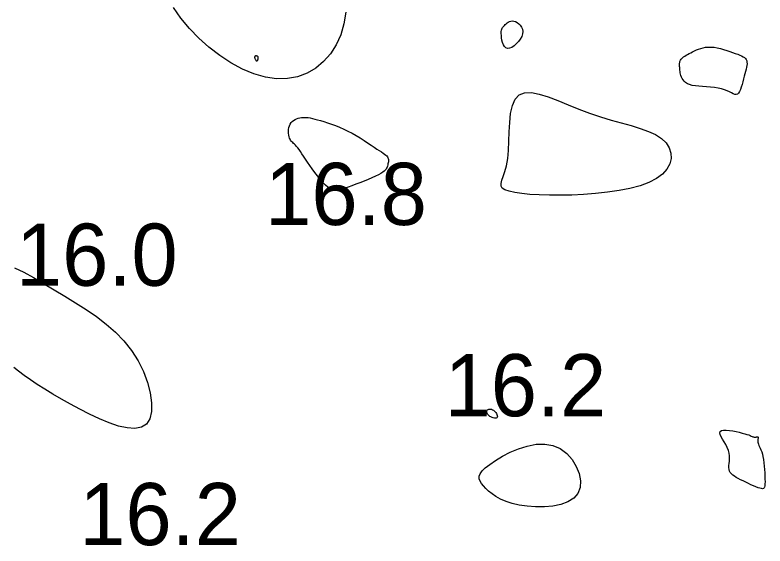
# Model space of a CAD drawing. Extents: x 3040093 to 3056816, y 408076 to 509144.
# Drawn here: x 3045926.6 to 3045987, y 434548.7 to 434591.4 of the extents above; entities that cross this region are included whole.
import ezdxf

# ---------------------------------------------------------------- set-up
doc = ezdxf.new("R2010")
doc.units = 0
doc.layers.add('V-CHAN-CONT-EL17', color=7, linetype='Continuous')
doc.layers.add('V-TOPO-SOUN-0610', color=7, linetype='Continuous')

msp = doc.modelspace()

# ---------------------------------------------------------------- linework, layer by layer
at = {"layer": 'V-CHAN-CONT-EL17'}
for points in [[(3045953.24, 434591.64), (3045953.079, 434590.693), (3045952.821, 434589.81), (3045952.46, 434589.003), (3045951.999, 434588.283), (3045951.448, 434587.657), (3045950.817, 434587.136), (3045950.113, 434586.728), (3045949.347, 434586.441), (3045948.527, 434586.286), (3045947.662, 434586.272), (3045946.762, 434586.403), (3045945.841, 434586.67), (3045944.912, 434587.058), (3045943.99, 434587.553), (3045943.088, 434588.142), (3045942.221, 434588.811), (3045941.403, 434589.545), (3045940.648, 434590.331), (3045939.967, 434591.156), (3045939.356, 434592.013)], [(3045926.587, 434571.056), (3045927.318, 434570.708), (3045928.098, 434570.281), (3045928.914, 434569.8), (3045929.757, 434569.293), (3045930.616, 434568.778), (3045931.479, 434568.253), (3045932.331, 434567.711), (3045933.161, 434567.141), (3045933.956, 434566.535), (3045934.701, 434565.885), (3045935.386, 434565.182), (3045935.996, 434564.417), (3045936.519, 434563.588), (3045936.949, 434562.722), (3045937.279, 434561.848), (3045937.501, 434560.999), (3045937.611, 434560.207), (3045937.6, 434559.503), (3045937.463, 434558.919), (3045937.194, 434558.487), (3045936.789, 434558.23), (3045936.266, 434558.134), (3045935.647, 434558.176), (3045934.951, 434558.334), (3045934.201, 434558.586), (3045933.417, 434558.91), (3045932.621, 434559.282), (3045931.833, 434559.68), (3045931.073, 434560.086), (3045930.347, 434560.492), (3045929.658, 434560.894), (3045929.011, 434561.291), (3045928.409, 434561.677), (3045927.855, 434562.05), (3045927.355, 434562.406), (3045926.911, 434562.741), (3045926.526, 434563.053)]]:
    msp.add_lwpolyline(points, dxfattribs=at)
for points in [[(3045966.1, 434588.76), (3045965.99, 434588.863), (3045965.904, 434589.008), (3045965.838, 434589.183), (3045965.792, 434589.375), (3045965.761, 434589.572), (3045965.744, 434589.762), (3045965.739, 434589.932), (3045965.742, 434590.071), (3045965.754, 434590.184), (3045965.775, 434590.274), (3045965.803, 434590.347), (3045965.839, 434590.408), (3045965.882, 434590.463), (3045965.932, 434590.516), (3045965.99, 434590.573), (3045966.054, 434590.637), (3045966.125, 434590.705), (3045966.205, 434590.772), (3045966.292, 434590.833), (3045966.388, 434590.883), (3045966.494, 434590.917), (3045966.611, 434590.93), (3045966.737, 434590.916), (3045966.874, 434590.873), (3045967.013, 434590.801), (3045967.147, 434590.702), (3045967.268, 434590.579), (3045967.367, 434590.435), (3045967.435, 434590.27), (3045967.465, 434590.088), (3045967.449, 434589.892), (3045967.38, 434589.683), (3045967.267, 434589.473), (3045967.12, 434589.269), (3045966.949, 434589.083), (3045966.764, 434588.924), (3045966.577, 434588.803), (3045966.397, 434588.729), (3045966.235, 434588.713)], [(3045980.322, 434587.971), (3045980.405, 434588.035), (3045980.5, 434588.1), (3045980.607, 434588.167), (3045980.725, 434588.235), (3045980.853, 434588.305), (3045980.989, 434588.376), (3045981.133, 434588.449), (3045981.284, 434588.523), (3045981.442, 434588.596), (3045981.609, 434588.664), (3045981.786, 434588.724), (3045981.974, 434588.774), (3045982.174, 434588.81), (3045982.387, 434588.83), (3045982.614, 434588.829), (3045982.855, 434588.807), (3045983.106, 434588.765), (3045983.363, 434588.708), (3045983.621, 434588.64), (3045983.875, 434588.563), (3045984.12, 434588.482), (3045984.352, 434588.4), (3045984.565, 434588.321), (3045984.756, 434588.248), (3045984.925, 434588.18), (3045985.071, 434588.113), (3045985.196, 434588.045), (3045985.299, 434587.975), (3045985.38, 434587.899), (3045985.442, 434587.814), (3045985.482, 434587.719), (3045985.504, 434587.611), (3045985.507, 434587.49), (3045985.495, 434587.355), (3045985.471, 434587.207), (3045985.435, 434587.045), (3045985.391, 434586.869), (3045985.341, 434586.679), (3045985.288, 434586.475), (3045985.232, 434586.258), (3045985.174, 434586.035), (3045985.114, 434585.815), (3045985.049, 434585.606), (3045984.979, 434585.415), (3045984.904, 434585.253), (3045984.822, 434585.126), (3045984.734, 434585.043), (3045984.636, 434585.01), (3045984.527, 434585.021), (3045984.404, 434585.065), (3045984.264, 434585.135), (3045984.102, 434585.219), (3045983.916, 434585.311), (3045983.703, 434585.399), (3045983.46, 434585.475), (3045983.185, 434585.532), (3045982.886, 434585.573), (3045982.572, 434585.602), (3045982.252, 434585.624), (3045981.936, 434585.645), (3045981.632, 434585.668), (3045981.35, 434585.7), (3045981.1, 434585.744), (3045980.887, 434585.805), (3045980.711, 434585.882), (3045980.568, 434585.971), (3045980.453, 434586.071), (3045980.362, 434586.18), (3045980.292, 434586.293), (3045980.238, 434586.411), (3045980.196, 434586.528), (3045980.163, 434586.645), (3045980.138, 434586.759), (3045980.119, 434586.871), (3045980.105, 434586.979), (3045980.096, 434587.082), (3045980.091, 434587.181), (3045980.088, 434587.275), (3045980.087, 434587.363), (3045980.086, 434587.444), (3045980.089, 434587.519), (3045980.095, 434587.59), (3045980.108, 434587.657), (3045980.128, 434587.721), (3045980.158, 434587.784), (3045980.199, 434587.846), (3045980.253, 434587.908)], [(3045946.102, 434587.719), (3045946.122, 434587.744), (3045946.14, 434587.778), (3045946.156, 434587.818), (3045946.168, 434587.862), (3045946.178, 434587.906), (3045946.184, 434587.948), (3045946.187, 434587.985), (3045946.186, 434588.015), (3045946.181, 434588.037), (3045946.174, 434588.054), (3045946.165, 434588.066), (3045946.154, 434588.074), (3045946.143, 434588.079), (3045946.132, 434588.082), (3045946.122, 434588.084), (3045946.112, 434588.087), (3045946.103, 434588.089), (3045946.095, 434588.092), (3045946.087, 434588.095), (3045946.079, 434588.098), (3045946.07, 434588.101), (3045946.061, 434588.105), (3045946.051, 434588.108), (3045946.039, 434588.111), (3045946.026, 434588.114), (3045946.013, 434588.116), (3045945.999, 434588.117), (3045945.984, 434588.117), (3045945.97, 434588.115), (3045945.955, 434588.111), (3045945.942, 434588.104), (3045945.929, 434588.095), (3045945.917, 434588.082), (3045945.908, 434588.067), (3045945.9, 434588.048), (3045945.896, 434588.025), (3045945.896, 434587.999), (3045945.899, 434587.968), (3045945.907, 434587.934), (3045945.919, 434587.895), (3045945.936, 434587.855), (3045945.957, 434587.815), (3045945.98, 434587.778), (3045946.004, 434587.746), (3045946.03, 434587.722), (3045946.055, 434587.708), (3045946.079, 434587.707)], [(3045967.61, 434585.156), (3045968.156, 434585.167), (3045968.795, 434585.045), (3045969.511, 434584.821), (3045970.288, 434584.524), (3045971.113, 434584.185), (3045971.968, 434583.834), (3045972.838, 434583.502), (3045973.709, 434583.212), (3045974.566, 434582.958), (3045975.395, 434582.727), (3045976.182, 434582.506), (3045976.913, 434582.283), (3045977.573, 434582.045), (3045978.15, 434581.779), (3045978.627, 434581.472), (3045978.995, 434581.116), (3045979.247, 434580.72), (3045979.383, 434580.296), (3045979.4, 434579.859), (3045979.295, 434579.422), (3045979.066, 434578.997), (3045978.712, 434578.598), (3045978.229, 434578.238), (3045977.619, 434577.928), (3045976.9, 434577.666), (3045976.09, 434577.45), (3045975.211, 434577.276), (3045974.283, 434577.139), (3045973.327, 434577.037), (3045972.362, 434576.966), (3045971.409, 434576.921), (3045970.487, 434576.901), (3045969.611, 434576.902), (3045968.793, 434576.926), (3045968.045, 434576.971), (3045967.382, 434577.035), (3045966.816, 434577.119), (3045966.36, 434577.221), (3045966.026, 434577.341), (3045965.822, 434577.479), (3045965.731, 434577.645), (3045965.729, 434577.85), (3045965.793, 434578.105), (3045965.901, 434578.422), (3045966.029, 434578.81), (3045966.155, 434579.282), (3045966.255, 434579.849), (3045966.314, 434580.513), (3045966.346, 434581.246), (3045966.372, 434582.01), (3045966.414, 434582.767), (3045966.493, 434583.48), (3045966.632, 434584.112), (3045966.851, 434584.625), (3045967.171, 434584.981)], [(3045949.987, 434579.819), (3045949.837, 434580.041), (3045949.701, 434580.241), (3045949.578, 434580.419), (3045949.466, 434580.577), (3045949.364, 434580.714), (3045949.271, 434580.832), (3045949.185, 434580.931), (3045949.105, 434581.012), (3045949.031, 434581.081), (3045948.962, 434581.141), (3045948.899, 434581.199), (3045948.841, 434581.258), (3045948.79, 434581.324), (3045948.744, 434581.403), (3045948.704, 434581.498), (3045948.67, 434581.614), (3045948.644, 434581.747), (3045948.628, 434581.892), (3045948.622, 434582.044), (3045948.63, 434582.199), (3045948.653, 434582.351), (3045948.692, 434582.496), (3045948.749, 434582.629), (3045948.826, 434582.745), (3045948.92, 434582.845), (3045949.028, 434582.93), (3045949.147, 434583.001), (3045949.274, 434583.058), (3045949.406, 434583.103), (3045949.54, 434583.136), (3045949.673, 434583.158), (3045949.804, 434583.17), (3045949.934, 434583.173), (3045950.068, 434583.166), (3045950.211, 434583.148), (3045950.367, 434583.121), (3045950.539, 434583.083), (3045950.732, 434583.034), (3045950.951, 434582.976), (3045951.197, 434582.906), (3045951.469, 434582.825), (3045951.762, 434582.732), (3045952.072, 434582.627), (3045952.395, 434582.508), (3045952.727, 434582.376), (3045953.065, 434582.229), (3045953.404, 434582.068), (3045953.739, 434581.891), (3045954.069, 434581.705), (3045954.389, 434581.512), (3045954.697, 434581.318), (3045954.988, 434581.127), (3045955.26, 434580.945), (3045955.509, 434580.776), (3045955.731, 434580.625), (3045955.926, 434580.496), (3045956.092, 434580.386), (3045956.233, 434580.291), (3045956.351, 434580.209), (3045956.446, 434580.135), (3045956.521, 434580.065), (3045956.578, 434579.998), (3045956.619, 434579.927), (3045956.645, 434579.852), (3045956.659, 434579.772), (3045956.662, 434579.688), (3045956.655, 434579.602), (3045956.642, 434579.515), (3045956.623, 434579.427), (3045956.6, 434579.34), (3045956.575, 434579.256), (3045956.549, 434579.174), (3045956.516, 434579.093), (3045956.472, 434579.012), (3045956.409, 434578.929), (3045956.321, 434578.843), (3045956.204, 434578.751), (3045956.05, 434578.652), (3045955.853, 434578.544), (3045955.61, 434578.426), (3045955.33, 434578.301), (3045955.021, 434578.172), (3045954.695, 434578.04), (3045954.361, 434577.91), (3045954.031, 434577.784), (3045953.713, 434577.666), (3045953.42, 434577.557), (3045953.157, 434577.462), (3045952.923, 434577.384), (3045952.711, 434577.329), (3045952.516, 434577.301), (3045952.331, 434577.304), (3045952.151, 434577.344), (3045951.97, 434577.425), (3045951.783, 434577.551), (3045951.584, 434577.725), (3045951.376, 434577.94), (3045951.164, 434578.187), (3045950.95, 434578.456), (3045950.738, 434578.739), (3045950.532, 434579.025), (3045950.336, 434579.307), (3045950.153, 434579.574)], [(3045964.683, 434559.672), (3045964.74, 434559.691), (3045964.804, 434559.698), (3045964.874, 434559.694), (3045964.948, 434559.677), (3045965.024, 434559.649), (3045965.099, 434559.607), (3045965.171, 434559.554), (3045965.238, 434559.488), (3045965.298, 434559.413), (3045965.349, 434559.334), (3045965.388, 434559.253), (3045965.414, 434559.176), (3045965.423, 434559.105), (3045965.415, 434559.045), (3045965.385, 434559), (3045965.335, 434558.973), (3045965.266, 434558.964), (3045965.184, 434558.969), (3045965.094, 434558.988), (3045965, 434559.02), (3045964.907, 434559.061), (3045964.82, 434559.112), (3045964.743, 434559.169), (3045964.68, 434559.231), (3045964.632, 434559.297), (3045964.599, 434559.364), (3045964.58, 434559.429), (3045964.574, 434559.492), (3045964.582, 434559.55), (3045964.604, 434559.6), (3045964.637, 434559.642)], [(3045985.334, 434557.714), (3045985.504, 434557.661), (3045985.645, 434557.612), (3045985.759, 434557.569), (3045985.852, 434557.53), (3045985.926, 434557.498), (3045985.986, 434557.471), (3045986.036, 434557.451), (3045986.079, 434557.438), (3045986.116, 434557.43), (3045986.149, 434557.427), (3045986.179, 434557.429), (3045986.205, 434557.433), (3045986.23, 434557.44), (3045986.253, 434557.447), (3045986.276, 434557.455), (3045986.3, 434557.461), (3045986.323, 434557.466), (3045986.345, 434557.469), (3045986.364, 434557.467), (3045986.381, 434557.461), (3045986.394, 434557.45), (3045986.401, 434557.432), (3045986.403, 434557.407), (3045986.399, 434557.374), (3045986.391, 434557.333), (3045986.38, 434557.284), (3045986.371, 434557.229), (3045986.365, 434557.168), (3045986.365, 434557.1), (3045986.372, 434557.027), (3045986.391, 434556.948), (3045986.422, 434556.865), (3045986.464, 434556.773), (3045986.514, 434556.67), (3045986.57, 434556.553), (3045986.628, 434556.418), (3045986.686, 434556.262), (3045986.741, 434556.082), (3045986.791, 434555.875), (3045986.834, 434555.638), (3045986.87, 434555.38), (3045986.898, 434555.108), (3045986.921, 434554.831), (3045986.937, 434554.558), (3045986.947, 434554.297), (3045986.953, 434554.056), (3045986.954, 434553.845), (3045986.951, 434553.67), (3045986.94, 434553.531), (3045986.919, 434553.425), (3045986.884, 434553.35), (3045986.833, 434553.305), (3045986.761, 434553.287), (3045986.666, 434553.293), (3045986.545, 434553.323), (3045986.396, 434553.373), (3045986.222, 434553.44), (3045986.03, 434553.521), (3045985.826, 434553.613), (3045985.614, 434553.711), (3045985.4, 434553.814), (3045985.191, 434553.917), (3045984.992, 434554.016), (3045984.807, 434554.111), (3045984.639, 434554.202), (3045984.489, 434554.293), (3045984.359, 434554.386), (3045984.25, 434554.484), (3045984.163, 434554.59), (3045984.1, 434554.708), (3045984.063, 434554.84), (3045984.051, 434554.988), (3045984.057, 434555.151), (3045984.074, 434555.328), (3045984.092, 434555.518), (3045984.103, 434555.72), (3045984.099, 434555.931), (3045984.072, 434556.15), (3045984.013, 434556.377), (3045983.918, 434556.608), (3045983.797, 434556.838), (3045983.665, 434557.063), (3045983.537, 434557.276), (3045983.427, 434557.471), (3045983.349, 434557.643), (3045983.32, 434557.786), (3045983.352, 434557.893), (3045983.456, 434557.962), (3045983.623, 434557.996), (3045983.838, 434558), (3045984.086, 434557.98), (3045984.353, 434557.942), (3045984.626, 434557.891), (3045984.889, 434557.832), (3045985.129, 434557.772)], [(3045970.477, 434556.513), (3045971, 434556.121), (3045971.437, 434555.634), (3045971.776, 434555.083), (3045972.005, 434554.501), (3045972.11, 434553.922), (3045972.079, 434553.378), (3045971.899, 434552.901), (3045971.565, 434552.518), (3045971.098, 434552.226), (3045970.529, 434552.02), (3045969.888, 434551.889), (3045969.203, 434551.827), (3045968.504, 434551.826), (3045967.822, 434551.877), (3045967.185, 434551.973), (3045966.618, 434552.105), (3045966.12, 434552.268), (3045965.687, 434552.455), (3045965.313, 434552.659), (3045964.993, 434552.873), (3045964.721, 434553.093), (3045964.492, 434553.31), (3045964.301, 434553.52), (3045964.144, 434553.716), (3045964.03, 434553.905), (3045963.969, 434554.093), (3045963.97, 434554.286), (3045964.045, 434554.492), (3045964.202, 434554.716), (3045964.453, 434554.966), (3045964.808, 434555.249), (3045965.272, 434555.566), (3045965.827, 434555.897), (3045966.454, 434556.217), (3045967.129, 434556.501), (3045967.831, 434556.724), (3045968.538, 434556.861), (3045969.229, 434556.886), (3045969.883, 434556.775)]]:
    msp.add_lwpolyline(points, close=True, dxfattribs=at)

# ---------------------------------------------------------------- texts
at = {"layer": 'V-TOPO-SOUN-0610'}
for s, p in [('16.8 ', (3045946.743, 434574.51)), ('16.0 ', (3045926.693, 434569.62)), ('16.2 ', (3045961.173, 434559.12)), ('16.2 ', (3045931.783, 434548.75))]:
    msp.add_text(s, height=5, dxfattribs=at).set_placement(p)

doc.saveas('drawing.dxf')
